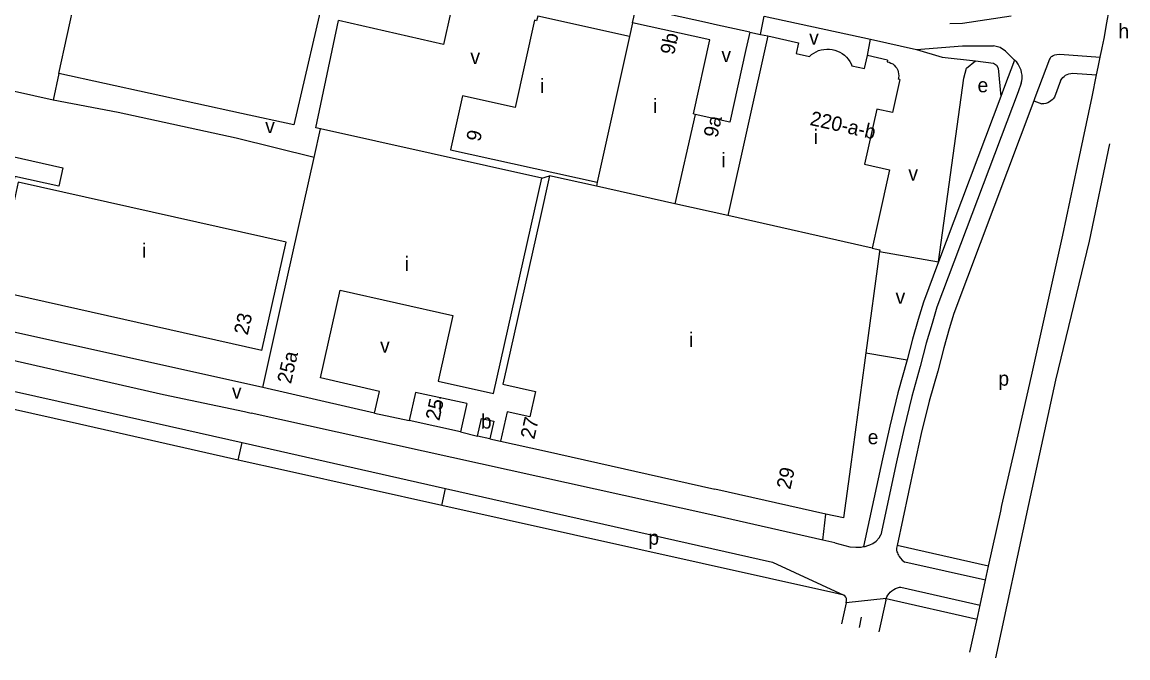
# Model space of a CAD drawing. Extents: x 161775 to 163181, y 382878 to 383925.
# Drawn here: x 162855 to 163161.9, y 382878.4 to 383054.8 of the extents above; entities that cross this region are included whole.
import ezdxf

# ---------------------------------------------------------------- set-up
doc = ezdxf.new("R2010")
doc.units = 0
for name, color, linetype in [('BLT_Basislijn', 7, 'Continuous'), ('BLT_Bebouwing', 7, 'Continuous'), ('BLT_Centroide', 7, 'Continuous'), ('BLT_Huisnummer', 7, 'Continuous'), ('BLT_Huisnummer_reeks', 7, 'Continuous'), ('BLT_Onderverdeling_panden', 7, 'Continuous'), ('BLT_Vlakafsluiter', 7, 'Continuous')]:
    doc.layers.add(name, color=color, linetype=linetype)

msp = doc.modelspace()

# ---------------------------------------------------------------- linework, layer by layer
at = {"layer": 'BLT_Basislijn'}
for p, q in [((163156.06, 383054.6), (163157.63, 383063.17)), ((163045.19, 383054.61), (163025.39, 383058.97)), ((163047.17, 383054.17), (163045.19, 383054.61)), ((163056.98, 383052.07), (163047.17, 383054.17)), ((163059.92, 383051.41), (163060.96, 383056.51)), ((163060.96, 383056.51), (163090.48, 383050.06)), ((163112.52, 383054.45), (163116, 383054.57)), ((163116, 383054.57), (163129.46, 383056.55)), ((163155.27, 383050.3), (163156.06, 383054.6)), ((163089.59, 383045.51), (163090.48, 383050.06)), ((163090.48, 383050.06), (163103.2, 383047.25)), ((163103.2, 383047.25), (163115.99, 383048.21)), ((163115.99, 383048.21), (163124.62, 383048.28)), ((163154.2, 383045.09), (163155.27, 383050.3)), ((163103.2, 383047.25), (163110.35, 383045.09)), ((163110.35, 383045.09), (163119.6, 383044.03)), ((163153.62, 383042.29), (163154.2, 383045.09)), ((163154.29, 383045.53), (163154.63, 383047.19)), ((163119.6, 383044.03), (163124.57, 383043.46)), ((163124.57, 383043.46), (163125.43, 383042.91)), ((163125.43, 383042.91), (163125.89, 383042)), ((163125.89, 383042), (163126.62, 383034.16)), ((162881.64, 383029.73), (162863.57, 383033.17)), ((163126.62, 383034.16), (163109.35, 382988.31)), ((163135.78, 383032.93), (163138, 383032.13)), ((162999.19, 383011.55), (163001.36, 383012.18)), ((163092.95, 382991.2), (163109.35, 382988.31)), ((162921.78, 382953.42), (162830.29, 382973.75)), ((163089.14, 382963.06), (163100.61, 382961.05)), ((163045.85, 382918.17), (162918.58, 382946.29)), ((162952.77, 382946.3), (162962.44, 382944.23)), ((162976.63, 382941.1), (162981.4, 382939.92)), ((162914.91, 382933.28), (162916.01, 382938.15)), ((162916.01, 382938.15), (162972.49, 382925.41)), ((162984.78, 382939.17), (162987.75, 382938.55)), ((162928.31, 382930.25), (162914.91, 382933.28)), ((162971.44, 382920.65), (162928.31, 382930.25)), ((162971.44, 382920.65), (162972.49, 382925.41)), ((163123.25, 382903.81), (163126.59, 382919.11)), ((163126.59, 382919.11), (163126.95, 382920.69)), ((163077.24, 382911.04), (163045.85, 382918.17)), ((163077.24, 382911.04), (163078.06, 382918.3)), ((163080.59, 382910.28), (163077.24, 382911.04)), ((163123.25, 382903.81), (163097.82, 382909.53)), ((163122.4, 382899.9), (163099.96, 382904.94)), ((163122.4, 382899.9), (163123.25, 382903.81)), ((163098.89, 382897.98), (163120.9, 382893.04)), ((163120.9, 382893.04), (163122.4, 382899.9)), ((163094.69, 382894.38), (163092.78, 382885.56)), ((163094.83, 382894.82), (163120.05, 382889.15)), ((163083.67, 382893.63), (163082.42, 382887.86)), ((163120.05, 382889.15), (163120.9, 382893.04)), ((163087.88, 382889.66), (163087.27, 382886.78)), ((163118.05, 382879.97), (163120.05, 382889.15))]:
    msp.add_line(p, q, dxfattribs=at)
for points in [[(162977.75, 383074.78), (162971.96, 383048.61), (162942.83, 383055.25)], [(162937.75, 383025.21), (162936.51, 383025.52), (162942.83, 383055.25)], [(163130.44, 383044.27), (163127.96, 383046.73), (163126.43, 383047.79), (163124.62, 383048.28)], [(163140.43, 383045.03), (163140.3, 383044.81), (163140.15, 383044.54), (163136.09, 383033.77), (163135.78, 383032.93)], [(163140.43, 383045.03), (163140.65, 383045.25), (163140.85, 383045.39), (163141.2, 383045.56), (163141.63, 383045.71), (163142.13, 383045.82), (163142.99, 383045.9)], [(163142.99, 383045.9), (163154.2, 383045.09)], [(163109.35, 382988.31), (163116.33, 383039.26), (163117.11, 383042.03), (163119.6, 383044.03)], [(163130.44, 383044.27), (163127.66, 383036.91), (163126.62, 383034.16)], [(163132.29, 383037.84), (163132.45, 383038.48), (163132.53, 383039.17), (163132.53, 383040.11), (163132.4, 383040.86), (163132.28, 383041.47), (163132.03, 383042.07), (163131.76, 383042.63), (163131.44, 383043.15), (163131.05, 383043.66), (163130.44, 383044.27)], [(163153.18, 383040.15), (163153.62, 383042.29)], [(163126.95, 382920.69), (163131.01, 382938.23), (163135.35, 382957.37), (163139.61, 382976.53), (163143.8, 382995.71), (163147.91, 383014.9), (163151.94, 383034.11), (163153.18, 383040.15)], [(163143.22, 383038.49), (163141.52, 383033.98)], [(163143.22, 383038.49), (163143.53, 383039.04), (163143.84, 383039.44), (163144.17, 383039.77), (163144.58, 383040.09), (163145.01, 383040.3), (163145.51, 383040.5), (163146.02, 383040.6), (163146.55, 383040.63)], [(163146.55, 383040.63), (163153.18, 383040.15)], [(163132.29, 383037.84), (163131.4, 383035.5), (163108.88, 382975.72)], [(163135.78, 383032.93), (163113.57, 382973.99)], [(163141.52, 383033.98), (163141.14, 383033.53), (163140.87, 383033.24), (163140.5, 383032.95), (163140.13, 383032.69), (163139.68, 383032.46), (163139.1, 383032.27), (163138.55, 383032.15), (163138.28, 383032.1), (163138, 383032.13)], [(162935.99, 383017.27), (162914.37, 383022.57), (162881.64, 383029.73)], [(163141.94, 382955.48), (163151.25, 382993.99), (163156.91, 383021.07)], [(162617.86, 383004.88), (162744.93, 382976.48), (162872.01, 382948.08), (162916.01, 382938.15)], [(163109.35, 382988.31), (163105.14, 382977.13)], [(163105.14, 382977.13), (163103.69, 382972.25), (163102.09, 382966.78), (163100.61, 382961.05)], [(163108.88, 382975.72), (163107.53, 382971.13), (163105.95, 382965.72), (163104.28, 382959.24), (163101.94, 382950.88), (163099.69, 382941.75), (163097.67, 382932.79), (163093.34, 382912.49)], [(163113.57, 382973.99), (163112.33, 382969.73), (163110.77, 382964.39), (163109.11, 382957.94), (163106.77, 382949.61), (163104.55, 382940.61), (163102.55, 382931.72), (163097.82, 382909.53)], [(162914.91, 382933.28), (162870.92, 382943.21), (162743.84, 382971.6)], [(162836.21, 382964.67), (162836.84, 382964.53), (162894.26, 382951.48), (162916.67, 382946.71), (162918.58, 382946.29)], [(163100.61, 382961.05), (163098.07, 382951.9), (163095.79, 382942.67), (163093.76, 382933.64), (163088.55, 382909.24)], [(163125.27, 382878.37), (163134.44, 382920.93), (163141.94, 382955.48)], [(162972.49, 382925.41), (163063.21, 382904.93), (163083.06, 382895.81)], [(163083.06, 382895.81), (163080.28, 382896.42), (162971.44, 382920.65)], [(163088.55, 382909.24), (163088.94, 382909.3), (163089.69, 382909.55), (163090.31, 382909.75), (163091.12, 382910.16), (163091.99, 382910.79), (163092.82, 382911.69), (163093.34, 382912.49)], [(163080.59, 382910.28), (163084.7, 382909.22), (163086.39, 382909.14), (163087.84, 382909.14), (163088.55, 382909.24)], [(163097.82, 382909.53), (163097.67, 382908.85), (163097.65, 382908.58), (163097.68, 382908.24), (163097.78, 382907.83), (163097.91, 382907.51), (163098.05, 382907.18), (163098.2, 382906.84), (163098.41, 382906.52), (163098.8, 382906.04), (163099.29, 382905.49), (163099.61, 382905.18), (163099.96, 382904.94)], [(163094.83, 382894.82), (163095.02, 382895.3), (163095.26, 382895.76), (163095.62, 382896.24), (163095.95, 382896.63), (163096.37, 382897), (163096.89, 382897.35), (163097.36, 382897.61), (163097.97, 382897.83), (163098.52, 382897.96), (163098.89, 382897.98)], [(163083.67, 382893.63), (163083.81, 382894.3), (163083.75, 382894.85), (163083.59, 382895.24), (163083.36, 382895.58), (163083.06, 382895.81)], [(163094.69, 382894.38), (163094.83, 382894.82)]]:
    msp.add_lwpolyline(points, dxfattribs=at)
at = {"layer": 'BLT_Bebouwing'}
for p, q in [((163056.98, 383052.07), (163059.92, 383051.41)), ((163088.79, 383041.9), (163089.59, 383045.51)), ((163095.19, 383044.26), (163089.59, 383045.51)), ((163085.29, 383042.68), (163088.79, 383041.9)), ((163095.19, 383044.26), (163095.09, 383043.81)), ((162865.2, 383040.6), (162863.57, 383033.17)), ((163098.63, 383038.93), (163096.59, 383029.69)), ((163098.63, 383038.93), (163098.16, 383039.03)), ((163051.43, 383027.09), (163041.8, 383029.22)), ((163096.59, 383029.69), (163092.2, 383030.67)), ((162935.99, 383017.27), (162937.75, 383025.21)), ((162921.47, 382963.71), (162928.23, 382993.76)), ((163092.95, 382991.2), (163089.14, 382963.06)), ((162921.47, 382963.71), (162848.51, 382980.03)), ((163089.14, 382963.06), (163088.76, 382960.25)), ((163088.76, 382960.25), (163084.86, 382931.43)), ((162952.77, 382946.3), (162921.78, 382953.42)), ((162964.18, 382952.07), (162962.44, 382944.23)), ((162978.37, 382948.94), (162964.18, 382952.07)), ((162997.44, 382952.3), (162995.86, 382945.26)), ((162978.37, 382948.94), (162976.63, 382941.1)), ((162976.63, 382941.1), (162962.44, 382944.23)), ((162984.78, 382939.17), (162981.4, 382939.92))]:
    msp.add_line(p, q, dxfattribs=at)
for points in [[(162939.59, 383065.83), (162930.37, 383026.33), (162915.89, 383029.5), (162865.2, 383040.6)], [(163024.43, 383054.61), (163025.39, 383058.97)], [(162998.08, 383056.46), (162997.76, 383055.19), (162997.19, 383055.34), (162991.82, 383031.15), (162977.21, 383034.39), (162973.91, 383019.4), (163014.61, 383010.44)], [(163041.8, 383029.22), (163041.28, 383029.34), (163045.84, 383049.86), (163024.43, 383054.61)], [(163056.98, 383052.07), (163055.89, 383047.19), (163051.43, 383027.09)], [(163059.92, 383051.41), (163061.92, 383050.97)], [(163061.92, 383050.97), (163070.45, 383049.07), (163069.8, 383046.12), (163073.49, 383045.3)], [(163073.49, 383045.3), (163074.07, 383045.79), (163074.69, 383046.23), (163075.36, 383046.6), (163076.06, 383046.9), (163076.79, 383047.12), (163077.53, 383047.26), (163078.29, 383047.33), (163079.05, 383047.31), (163079.81, 383047.22), (163080.55, 383047.04), (163081.27, 383046.79), (163081.95, 383046.47), (163082.6, 383046.07), (163083.21, 383045.61), (163083.76, 383045.09), (163084.26, 383044.51), (163084.69, 383043.89), (163085.06, 383043.22), (163085.29, 383042.68)], [(163095.09, 383043.81), (163095.63, 383043.68), (163096.14, 383043.47), (163096.62, 383043.2), (163097.05, 383042.85), (163097.43, 383042.45), (163097.75, 383042), (163098, 383041.5), (163098.17, 383040.98), (163098.27, 383040.43), (163098.29, 383039.88), (163098.23, 383039.33), (163098.16, 383039.03)], [(162863.57, 383033.17), (162842.07, 383038.01)], [(163092.2, 383030.67), (163088.81, 383015.37), (163095.7, 383013.84), (163092.63, 383000), (163090.91, 382992.11)], [(162999.19, 383011.55), (162937.75, 383025.21)], [(162926.96, 382976.71), (162935.99, 383017.27)], [(162952.77, 382946.3), (162954.16, 382952.34), (162937.82, 382956.09), (162943.27, 382980.46), (162974.52, 382973.44), (162970.44, 382955.19), (162985.81, 382951.75), (162999.19, 383011.55)], [(163001.36, 383012.18), (162998.66, 383000), (162989.5, 382959.23), (162988.4, 382954.32), (162997.44, 382952.3)], [(163014.36, 383009.3), (163001.36, 383012.18)], [(162928.23, 382993.76), (162853.84, 383010.41), (162851.67, 383000), (162848.19, 382984.64)], [(163014.61, 383010.44), (163014.36, 383009.3)], [(163090.91, 382992.11), (163093.01, 382991.64), (163092.95, 382991.2)], [(162921.78, 382953.42), (162926.96, 382976.71)], [(162995.86, 382945.26), (162989.57, 382946.67), (162987.75, 382938.55)], [(162981.4, 382939.92), (162982.5, 382944.85), (162985.88, 382944.1), (162984.78, 382939.17)], [(162987.75, 382938.55), (163000, 382935.81), (163047.23, 382925.22)], [(163084.86, 382931.43), (163082.94, 382917.21), (163078.06, 382918.3)], [(163078.06, 382918.3), (163047.23, 382925.22)]]:
    msp.add_lwpolyline(points, dxfattribs=at)
msp.add_lwpolyline([(162847.03, 383009.29), (162849.06, 383018.28), (162866.27, 383014.4), (162865.12, 383009.31), (162852.99, 383011.97), (162852.12, 383008.14)], close=True, dxfattribs=at)
at = {"layer": 'BLT_Onderverdeling_panden'}
for p, q in [((162865.2, 383040.6), (162873.9, 383080.35)), ((163023.58, 383050.81), (162998.08, 383056.46)), ((163061.92, 383050.97), (163050.84, 383001.11)), ((163041.8, 383029.22), (163036.15, 383004.41)), ((163036.16, 383004.4), (163014.36, 383009.3)), ((163050.84, 383001.11), (163036.15, 383004.41)), ((163090.91, 382992.11), (163050.84, 383001.11))]:
    msp.add_line(p, q, dxfattribs=at)
for points in [[(163024.43, 383054.61), (163023.58, 383050.81)], [(163023.58, 383050.81), (163014.61, 383010.44)]]:
    msp.add_lwpolyline(points, dxfattribs=at)
at = {"layer": 'BLT_Vlakafsluiter'}
msp.add_line((163094.83, 382894.82), (163083.67, 382893.63), dxfattribs=at)

# ---------------------------------------------------------------- texts
at = {"layer": 'BLT_Centroide'}
for s, p in [('h', (163159.27, 383050.32)), ('v', (163073.43, 383048.58)), ('v', (162979.4, 383043.23)), ('v', (163049.07, 383043.74)), ('i', (162998.75, 383035.12)), ('e', (163120.17, 383035.34)), ('i', (163030.09, 383029.55)), ('v', (162922.44, 383024)), ('i', (163074.73, 383021)), ('i', (163049.03, 383014.56)), ('v', (163100.96, 383010.86)), ('i', (162888.27, 382989.44)), ('i', (162961.2, 382985.75)), ('v', (163097.42, 382976.65)), ('i', (163040.05, 382964.69)), ('v', (162954.34, 382963.09)), ('p', (163125.95, 382953.91)), ('v', (162913.21, 382950.33)), ('i', (162970.4, 382946.59)), ('b', (162982.31, 382942.02)), ('e', (163089.68, 382937.66)), ('p', (163028.79, 382909.77))]:
    msp.add_text(s, height=4, dxfattribs=at).set_placement(p)
at = {"layer": 'BLT_Huisnummer'}
for s, rotation, p in [('9b', 77.4769, (163035.91, 383045.54)), ('9a', 77.4804, (163047.94, 383022.54)), ('9', 77.4787, (162982.08, 383021.45)), ('23', 77.3268, (162917.58, 382967.77)), ('25a', 77.0607, (162929.58, 382954.25)), ('25', 77.462, (162970.76, 382944.01))]:
    msp.add_text(s, height=4, rotation=rotation, dxfattribs=at).set_placement(p)
at = {"layer": 'BLT_Huisnummer_reeks'}
for s, rotation, p in [('220-a-b', 347.3478, (163073.42, 383026.3)), ('27', 77.3695, (162997.12, 382938.86)), ('29', 77.3601, (163068.19, 382924.94))]:
    msp.add_text(s, height=4, rotation=rotation, dxfattribs=at).set_placement(p)

doc.saveas('drawing.dxf')
